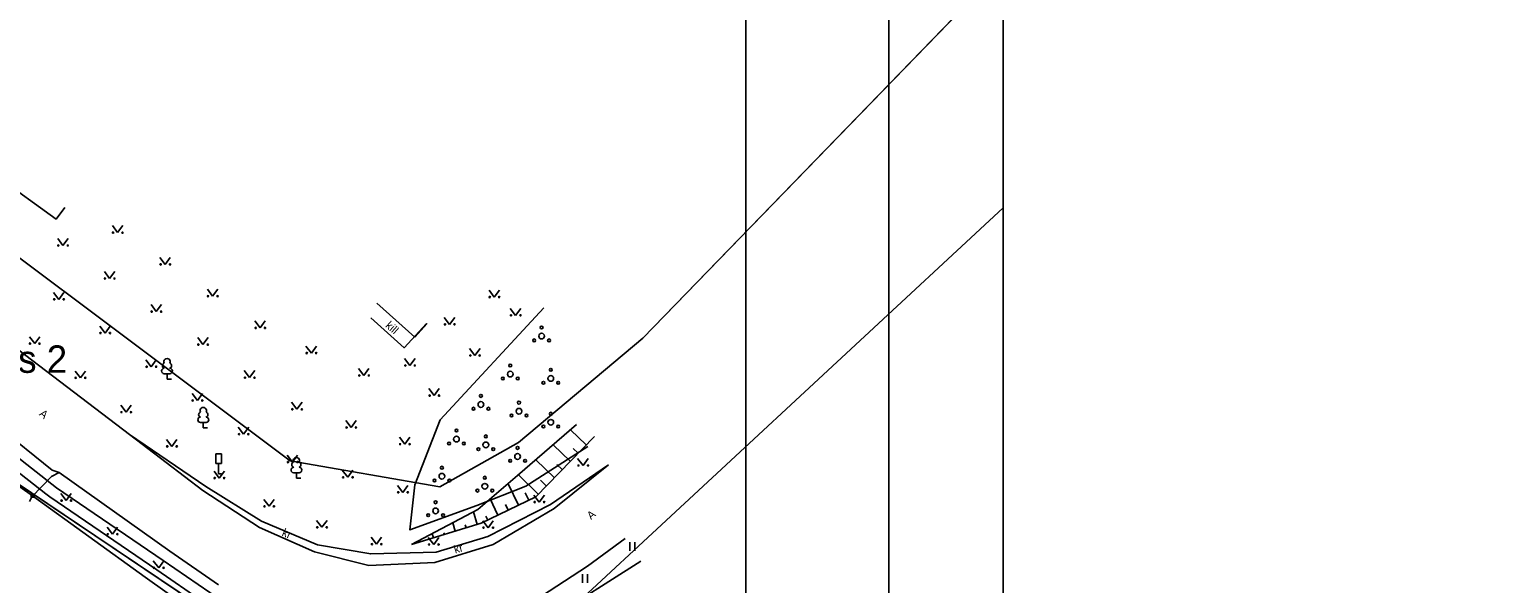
# Model space of a CAD drawing. Extents: x 554947 to 555436, y 6564938 to 6565792.
# Drawn here: x 555307.9 to 555435.7, y 6565528.1 to 6565576.6 of the extents above; entities that cross this region are included whole.
import ezdxf

# ---------------------------------------------------------------- set-up
doc = ezdxf.new("R2010")
doc.units = 0
for name, color, linetype in [('AED', 7, 'Continuous'), ('HALJASTUS', 7, 'Continuous'), ('KASUTUSALA', 7, 'Continuous'), ('LIIKLUS', 7, 'Continuous'), ('PIIR', 7, 'Continuous'), ('PR_SIDE', 7, 'Continuous'), ('PUU', 7, 'Continuous'), ('RELJEEF', 7, 'Continuous'), ('TEE', 7, 'Continuous'), ('VORMISTUS_3', 7, 'Continuous')]:
    doc.layers.add(name, color=color, linetype=linetype)

msp = doc.modelspace()

# ---------------------------------------------------------------- linework, layer by layer
at = {"layer": 'AED'}
for p, q in [((555304.52, 6565538.35), (555308.2, 6565535.79)), ((555308.07, 6565535.91), (555308.07, 6565535.66)), ((555308.07, 6565535.91), (555308.32, 6565535.91)), ((555308.32, 6565535.91), (555308.32, 6565535.66)), ((555308.07, 6565535.66), (555308.32, 6565535.66))]:
    msp.add_line(p, q, dxfattribs=at)
for points in [[(555338.31, 6565552.64), (555341.62, 6565549.67), (555342.69, 6565550.85)], [(555324, 6565524.39), (555318.05, 6565528.67), (555308.2, 6565535.79)]]:
    msp.add_lwpolyline(points, dxfattribs=at)
at = {"layer": 'HALJASTUS'}
for p, q in [((555315.17, 6565559.42), (555315.63, 6565558.81)), ((555315.63, 6565558.81), (555316.08, 6565559.42)), ((555310.39, 6565558.29), (555310.85, 6565557.68)), ((555310.85, 6565557.68), (555311.3, 6565558.29)), ((555319.32, 6565556.64), (555319.79, 6565556.03)), ((555319.79, 6565556.03), (555320.23, 6565556.64)), ((555314.47, 6565555.4), (555314.93, 6565554.79)), ((555314.93, 6565554.79), (555315.38, 6565555.4)), ((555323.48, 6565553.86), (555323.94, 6565553.25)), ((555323.94, 6565553.25), (555324.39, 6565553.86)), ((555310.03, 6565553.58), (555310.49, 6565552.97)), ((555310.49, 6565552.97), (555310.94, 6565553.58)), ((555348.11, 6565553.78), (555348.57, 6565553.17)), ((555348.57, 6565553.17), (555349.02, 6565553.78)), ((555318.55, 6565552.51), (555319.01, 6565551.9)), ((555319.01, 6565551.9), (555319.46, 6565552.51)), ((555344.2, 6565551.39), (555344.66, 6565550.78)), ((555344.66, 6565550.78), (555345.11, 6565551.39)), ((555349.97, 6565552.18), (555350.43, 6565551.57)), ((555350.43, 6565551.57), (555350.88, 6565552.18)), ((555314.07, 6565550.63), (555314.53, 6565550.02)), ((555314.53, 6565550.02), (555314.98, 6565550.63)), ((555327.63, 6565551.08), (555328.1, 6565550.47)), ((555328.1, 6565550.47), (555328.54, 6565551.08)), ((555307.91, 6565549.7), (555308.38, 6565549.1)), ((555308.38, 6565549.1), (555308.82, 6565549.7)), ((555322.63, 6565549.62), (555323.09, 6565549.01)), ((555323.09, 6565549.01), (555323.54, 6565549.62)), ((555332.1, 6565548.88), (555332.57, 6565548.27)), ((555332.57, 6565548.27), (555333.01, 6565548.88)), ((555318.11, 6565547.68), (555318.57, 6565547.07)), ((555318.57, 6565547.07), (555319.01, 6565547.68)), ((555340.73, 6565547.79), (555341.19, 6565547.18)), ((555341.19, 6565547.18), (555341.64, 6565547.79)), ((555346.41, 6565548.67), (555346.88, 6565548.06)), ((555346.88, 6565548.06), (555347.32, 6565548.67)), ((555311.91, 6565546.7), (555312.38, 6565546.1)), ((555312.38, 6565546.1), (555312.82, 6565546.7)), ((555326.71, 6565546.73), (555327.17, 6565546.12)), ((555327.17, 6565546.12), (555327.62, 6565546.73)), ((555336.7, 6565546.92), (555337.17, 6565546.31)), ((555337.17, 6565546.31), (555337.61, 6565546.92)), ((555342.85, 6565545.16), (555343.32, 6565544.55)), ((555343.32, 6565544.55), (555343.76, 6565545.16)), ((555315.91, 6565543.7), (555316.37, 6565543.1)), ((555316.37, 6565543.1), (555316.82, 6565543.7)), ((555322.14, 6565544.73), (555322.61, 6565544.12)), ((555322.61, 6565544.12), (555323.05, 6565544.73)), ((555330.85, 6565543.96), (555331.31, 6565543.35)), ((555331.31, 6565543.35), (555331.76, 6565543.96)), ((555335.59, 6565542.37), (555336.05, 6565541.76)), ((555336.05, 6565541.76), (555336.5, 6565542.37)), ((555326.18, 6565541.78), (555326.64, 6565541.17)), ((555326.64, 6565541.17), (555327.09, 6565541.78)), ((555319.91, 6565540.7), (555320.37, 6565540.1)), ((555320.37, 6565540.1), (555320.82, 6565540.7)), ((555340.28, 6565540.91), (555340.74, 6565540.3)), ((555340.74, 6565540.3), (555341.19, 6565540.91)), ((555330.46, 6565539.34), (555330.93, 6565538.73)), ((555330.93, 6565538.73), (555331.37, 6565539.34)), ((555355.86, 6565539.03), (555356.33, 6565538.43)), ((555356.33, 6565538.43), (555356.77, 6565539.03)), ((555324.06, 6565537.93), (555324.52, 6565537.33)), ((555324.52, 6565537.33), (555324.97, 6565537.93)), ((555335.28, 6565538.01), (555335.75, 6565537.4)), ((555335.75, 6565537.4), (555336.19, 6565538.01)), ((555310.67, 6565535.97), (555311.13, 6565535.36)), ((555311.13, 6565535.36), (555311.58, 6565535.97)), ((555340.1, 6565536.68), (555340.57, 6565536.08)), ((555340.57, 6565536.08), (555341.01, 6565536.68)), ((555328.41, 6565535.46), (555328.87, 6565534.86)), ((555328.87, 6565534.86), (555329.32, 6565535.46)), ((555352.04, 6565535.83), (555352.5, 6565535.23)), ((555352.5, 6565535.23), (555352.95, 6565535.83)), ((555333.03, 6565533.63), (555333.49, 6565533.02)), ((555333.49, 6565533.02), (555333.94, 6565533.63)), ((555347.57, 6565533.59), (555348.03, 6565532.99)), ((555348.03, 6565532.99), (555348.48, 6565533.59)), ((555314.71, 6565533.03), (555315.17, 6565532.42)), ((555315.17, 6565532.42), (555315.62, 6565533.03)), ((555337.81, 6565532.15), (555338.27, 6565531.55)), ((555338.27, 6565531.55), (555338.72, 6565532.15)), ((555342.8, 6565532.13), (555343.27, 6565531.52)), ((555343.27, 6565531.52), (555343.71, 6565532.13)), ((555360.41, 6565531.73), (555360.41, 6565530.97)), ((555360.86, 6565531.73), (555360.86, 6565530.97)), ((555318.75, 6565530.09), (555319.22, 6565529.48)), ((555319.22, 6565529.48), (555319.66, 6565530.09)), ((555356.27, 6565528.92), (555356.27, 6565528.16)), ((555356.72, 6565528.92), (555356.72, 6565528.16))]:
    msp.add_line(p, q, dxfattribs=at)
for points in [[(555352.89, 6565552.22), (555343.84, 6565542.42), (555341.63, 6565536.75), (555341.19, 6565532.8), (555347.05, 6565534.92), (555351.32, 6565536.63), (555356.76, 6565540.09)], [(555361.38, 6565530.07), (555353.3, 6565524.93), (555351.72, 6565521.85), (555350.97, 6565518.73), (555353.48, 6565515.91)]]:
    msp.add_lwpolyline(points, dxfattribs=at)
for centre in [(555310.45, 6565557.68), (555311.28, 6565557.68), (555315.23, 6565558.81), (555316.06, 6565558.81), (555319.39, 6565556.03), (555320.21, 6565556.03), (555314.53, 6565554.79), (555315.36, 6565554.79), (555310.09, 6565552.97), (555310.92, 6565552.97), (555323.54, 6565553.25), (555324.37, 6565553.25), (555348.17, 6565553.17), (555349, 6565553.17), (555318.61, 6565551.9), (555319.44, 6565551.9), (555350.03, 6565551.57), (555350.86, 6565551.57), (555314.13, 6565550.02), (555314.96, 6565550.02), (555327.7, 6565550.47), (555328.52, 6565550.47), (555344.26, 6565550.78), (555345.09, 6565550.78), (555307.97, 6565549.1), (555308.8, 6565549.1), (555322.69, 6565549.01), (555323.52, 6565549.01), (555332.17, 6565548.27), (555332.99, 6565548.27), (555346.47, 6565548.06), (555347.3, 6565548.06), (555311.97, 6565546.1), (555312.8, 6565546.1), (555318.17, 6565547.07), (555319, 6565547.07), (555326.77, 6565546.12), (555327.6, 6565546.12), (555336.77, 6565546.31), (555337.6, 6565546.31), (555340.79, 6565547.18), (555341.62, 6565547.18), (555322.2, 6565544.12), (555323.03, 6565544.12), (555342.92, 6565544.55), (555343.74, 6565544.55), (555315.97, 6565543.1), (555316.8, 6565543.1), (555330.91, 6565543.35), (555331.74, 6565543.35), (555326.24, 6565541.17), (555327.07, 6565541.17), (555335.65, 6565541.76), (555336.48, 6565541.76), (555319.97, 6565540.1), (555320.8, 6565540.1), (555340.34, 6565540.3), (555341.17, 6565540.3), (555330.53, 6565538.73), (555331.36, 6565538.73), (555355.93, 6565538.43), (555356.76, 6565538.43), (555324.12, 6565537.33), (555324.95, 6565537.33), (555335.35, 6565537.4), (555336.18, 6565537.4), (555340.17, 6565536.08), (555341, 6565536.08), (555310.73, 6565535.36), (555311.56, 6565535.36), (555328.47, 6565534.86), (555329.3, 6565534.86), (555352.1, 6565535.23), (555352.93, 6565535.23), (555314.77, 6565532.42), (555315.6, 6565532.42), (555333.09, 6565533.02), (555333.92, 6565533.02), (555347.63, 6565532.99), (555348.46, 6565532.99), (555337.87, 6565531.55), (555338.7, 6565531.55), (555342.87, 6565531.52), (555343.7, 6565531.52), (555318.82, 6565529.48), (555319.65, 6565529.48)]:
    msp.add_circle(centre, 0.055, dxfattribs=at)
at = {"layer": 'KASUTUSALA'}
msp.add_lwpolyline([(555304.52, 6565541), (555310.28, 6565536.49), (555319.62, 6565530.13), (555323.68, 6565527.32), (555324.11, 6565527.04), (555330.04, 6565523.57), (555332.04, 6565522.33), (555334.88, 6565520.64), (555337.95, 6565518.8), (555340.91, 6565516.06), (555343.38, 6565512.73), (555343.14, 6565512.46), (555338.79, 6565515.38), (555330.79, 6565520.76), (555305.2, 6565537.96)], dxfattribs=at)
at = {"layer": 'LIIKLUS'}
for p, q in [((555324.21, 6565539.45), (555324.21, 6565538.6)), ((555324.71, 6565539.45), (555324.21, 6565539.45)), ((555324.71, 6565538.6), (555324.21, 6565538.6)), ((555324.46, 6565538.6), (555324.46, 6565537.7)), ((555324.71, 6565539.45), (555324.71, 6565538.6)), ((555324.71, 6565537.7), (555324.46, 6565537.7))]:
    msp.add_line(p, q, dxfattribs=at)
at = {"layer": 'PIIR'}
for points in [[(555374.15, 6565660.24), (555410.9, 6565638.65), (555418.94, 6565635.85), (555435.71, 6565632.72), (555428.83, 6565620.98), (555419.65, 6565609.54), (555361.56, 6565549.57), (555350.68, 6565540.44), (555343.81, 6565536.56), (555330.71, 6565538.85), (555251.24, 6565598.48), (555234.35, 6565605.6), (555223.17, 6565668.21)], [(555144.16, 6565410.6), (555124.27, 6565454.45), (555113.82, 6565475.68), (555076.76, 6565542.38), (555065.78, 6565566.7), (555060.42, 6565583.26), (555057.22, 6565600.73), (555056.61, 6565622.91), (555063.43, 6565647.29), (555114.24, 6565634), (555129.77, 6565611.2), (555130.73, 6565621.32), (555138.66, 6565615.26), (555160.12, 6565598.86), (555193.24, 6565604.68), (555193.7, 6565602.7), (555225.47, 6565605.89), (555234.35, 6565605.6), (555251.24, 6565598.48), (555330.71, 6565538.85), (555343.81, 6565536.56), (555350.68, 6565540.44), (555361.56, 6565549.57), (555393.07, 6565582.1)], [(555393.07, 6565560.97), (555353.12, 6565523.87), (555343.14, 6565512.46), (555302.6, 6565539.71), (555242.37, 6565583.94), (555179.42, 6565586.32), (555138.98, 6565580.6), (555121.18, 6565602.26), (555116.17, 6565610.5), (555109.96, 6565624.83), (555093.56, 6565628.47), (555079.04, 6565618.4), (555074.13, 6565607.82), (555075.34, 6565593.24), (555091.74, 6565551.94), (555171.91, 6565394.64), (555191.35, 6565341.19), (555195.08, 6565294.61), (555195.28, 6565271.63), (555191.64, 6565237.48)], [(555393.07, 6565456.05), (555368.05, 6565461.11), (555358.8, 6565482.45), (555353.12, 6565523.87), (555393.07, 6565560.97)]]:
    msp.add_lwpolyline(points, dxfattribs=at)
msp.add_lwpolyline([(555153.01, 6565448.47), (555161.15, 6565451.45), (555173.66, 6565456.03), (555207.29, 6565506.14), (555287.77, 6565518.56), (555302.6, 6565539.71), (555343.14, 6565512.46), (555319.44, 6565481.04), (555323.07, 6565461.26), (555312.9, 6565433.84), (555316.84, 6565372.52), (555318.72, 6565342.57), (555320.51, 6565314.61), (555303.13, 6565302.54), (555208.78, 6565303.3), (555205.15, 6565297.11), (555200.72, 6565310.3), (555206.9, 6565339.44), (555221.23, 6565376.06), (555216.83, 6565392.35), (555207.22, 6565406.57)], close=True, dxfattribs=at)
at = {"layer": 'PR_SIDE'}
msp.add_lwpolyline([(555383.07, 6565448.91), (555372.33, 6565450.45), (555366.01, 6565452.34), (555363.26, 6565453.63), (555360.29, 6565456.79), (555356.82, 6565461.86), (555354.2, 6565468.75), (555353.75, 6565469.93), (555350.28, 6565487.81), (555348.6, 6565498.75), (555346.2, 6565508), (555346.03, 6565508.33), (555343.44, 6565510.97), (555340.16, 6565515.39), (555337.34, 6565518), (555334.37, 6565519.78), (555331.52, 6565521.47), (555329.52, 6565522.71), (555323.59, 6565526.19), (555323.12, 6565526.49), (555319.05, 6565529.3), (555309.69, 6565535.68), (555309.35, 6565535.94), (555304.35, 6565539.86)], dxfattribs=at)
at = {"layer": 'PUU'}
for p, q in [((555320.19, 6565546.46), (555319.71, 6565546.46)), ((555319.95, 6565545.99), (555319.95, 6565546.46)), ((555320.33, 6565545.99), (555319.95, 6565545.99)), ((555323.36, 6565542.2), (555322.88, 6565542.2)), ((555323.12, 6565541.72), (555323.12, 6565542.2)), ((555323.5, 6565541.72), (555323.12, 6565541.72)), ((555331.5, 6565537.8), (555331.02, 6565537.8)), ((555331.26, 6565537.33), (555331.26, 6565537.8)), ((555331.64, 6565537.33), (555331.26, 6565537.33))]:
    msp.add_line(p, q, dxfattribs=at)
for centre, radius in [((555352.71, 6565549.76), 0.25), ((555352.71, 6565550.51), 0.125), ((555352.06, 6565549.38), 0.125), ((555353.36, 6565549.38), 0.125), ((555349.32, 6565546.05), 0.125), ((555349.97, 6565546.43), 0.25), ((555349.97, 6565547.18), 0.125), ((555350.62, 6565546.05), 0.125), ((555353.51, 6565546.05), 0.25), ((555353.51, 6565546.8), 0.125), ((555352.86, 6565545.67), 0.125), ((555354.16, 6565545.67), 0.125), ((555347.4, 6565543.77), 0.25), ((555347.4, 6565544.52), 0.125), ((555350.73, 6565543.93), 0.125), ((555346.75, 6565543.4), 0.125), ((555348.05, 6565543.4), 0.125), ((555350.08, 6565542.81), 0.125), ((555350.73, 6565543.18), 0.25), ((555351.38, 6565542.81), 0.125), ((555353.51, 6565542.21), 0.25), ((555353.51, 6565542.96), 0.125), ((555345.26, 6565541.49), 0.125), ((555347.83, 6565540.98), 0.125), ((555352.86, 6565541.84), 0.125), ((555354.16, 6565541.84), 0.125), ((555344.61, 6565540.36), 0.125), ((555345.26, 6565540.74), 0.25), ((555345.91, 6565540.36), 0.125), ((555347.18, 6565539.86), 0.125), ((555347.83, 6565540.23), 0.25), ((555348.48, 6565539.86), 0.125), ((555350.61, 6565539.97), 0.125), ((555349.96, 6565538.84), 0.125), ((555350.61, 6565539.22), 0.25), ((555351.26, 6565538.84), 0.125), ((555343.34, 6565537.12), 0.125), ((555343.99, 6565537.49), 0.25), ((555343.99, 6565538.24), 0.125), ((555344.64, 6565537.12), 0.125), ((555347.74, 6565537.36), 0.125), ((555347.09, 6565536.23), 0.125), ((555347.74, 6565536.61), 0.25), ((555348.39, 6565536.23), 0.125), ((555343.44, 6565534.46), 0.25), ((555343.44, 6565535.21), 0.125), ((555342.79, 6565534.08), 0.125), ((555344.09, 6565534.08), 0.125)]:
    msp.add_circle(centre, radius, dxfattribs=at)
for centre, radius, start, end in [((555319.95, 6565547.51), 0.277, 332.5799, 207.4201), ((555319.71, 6565546.7), 0.238, 90.0016, 269.3953), ((555319.78, 6565547.16), 0.233, 109.0217, 253.1415), ((555320.12, 6565547.16), 0.233, 286.8508, 70.9859), ((555320.18, 6565546.7), 0.238, 270.6047, 89.9984), ((555322.88, 6565542.43), 0.238, 90.0016, 269.3953), ((555322.95, 6565542.89), 0.233, 109.0217, 253.1415), ((555323.12, 6565543.24), 0.277, 332.5799, 207.4201), ((555323.29, 6565542.89), 0.233, 286.8508, 70.9859), ((555323.36, 6565542.43), 0.238, 270.6047, 89.9984), ((555331.09, 6565538.5), 0.233, 109.0217, 253.1415), ((555331.26, 6565538.85), 0.277, 332.5799, 207.4201), ((555331.43, 6565538.5), 0.233, 286.8508, 70.9859), ((555331.03, 6565538.04), 0.238, 90.0016, 269.3953), ((555331.5, 6565538.04), 0.238, 270.6047, 89.9984)]:
    msp.add_arc(centre, radius, start, end, dxfattribs=at)
at = {"layer": 'RELJEEF'}
for p, q in [((555356.6, 6565540.23), (555355.24, 6565541.56)), ((555355.21, 6565538.8), (555353.72, 6565540.25)), ((555355.91, 6565539.52), (555355.48, 6565539.93)), ((555353.82, 6565537.36), (555352.2, 6565538.93)), ((555354.51, 6565538.08), (555354.05, 6565538.53)), ((555352.42, 6565535.93), (555350.68, 6565537.62)), ((555350.69, 6565534.96), (555349.78, 6565536.84)), ((555351.59, 6565535.4), (555351.28, 6565536.03)), ((555353.12, 6565536.65), (555352.62, 6565537.14)), ((555348.89, 6565534.09), (555348.21, 6565535.5)), ((555349.79, 6565534.52), (555349.55, 6565535.02)), ((555345.16, 6565532.68), (555344.94, 6565533.42)), ((555347.07, 6565533.26), (555346.74, 6565534.37)), ((555347.99, 6565533.65), (555347.82, 6565534)), ((555343.25, 6565532.1), (555343.14, 6565532.46)), ((555344.21, 6565532.39), (555344.16, 6565532.55)), ((555346.12, 6565532.97), (555346.03, 6565533.25)), ((555342.29, 6565531.8), (555342.28, 6565531.86))]:
    msp.add_line(p, q, dxfattribs=at)
for points in [[(555341.34, 6565531.51), (555347.14, 6565534.58), (555350.61, 6565537.56), (555355.77, 6565542.02)], [(555341.34, 6565531.51), (555347.42, 6565533.37), (555352.19, 6565535.69), (555357.33, 6565540.98)]]:
    msp.add_lwpolyline(points, dxfattribs=at)
at = {"layer": 'TEE'}
for points in [[(555272.68, 6565590.13), (555271.48, 6565588.08), (555270.52, 6565586.42), (555269.72, 6565584.61), (555268.98, 6565582.24), (555268.55, 6565578.95), (555269.5, 6565576.95), (555281.04, 6565568.1), (555297.77, 6565555.51), (555316.66, 6565541.13), (555323.07, 6565536.25), (555328.04, 6565533.01), (555332.84, 6565530.88), (555337.61, 6565529.69), (555343.36, 6565529.95), (555348.46, 6565531.53), (555353.8, 6565534.68), (555358.56, 6565538.5)], [(555293.36, 6565574.44), (555292.54, 6565573.05), (555305.07, 6565563.71), (555310.25, 6565559.99), (555311.01, 6565561)], [(555337.76, 6565551.34), (555340.69, 6565548.73), (555342.63, 6565550.87)], [(555324.45, 6565528), (555320.2, 6565530.94), (555310.53, 6565537.81), (555309.91, 6565538.03), (555305.17, 6565541.81)], [(555316.66, 6565541.13), (555323.34, 6565536.58), (555328.21, 6565533.55), (555333.12, 6565531.48), (555337.76, 6565530.7), (555343.48, 6565530.86), (555348.01, 6565532.22), (555353.48, 6565535.01), (555358.56, 6565538.5)], [(555310.53, 6565537.81), (555309.86, 6565537.47), (555308.14, 6565535.69), (555307.92, 6565535.29)], [(555360.02, 6565532.03), (555356.72, 6565529.61), (555352.04, 6565526.57), (555350.84, 6565524.29), (555349.9, 6565522.25), (555349.37, 6565518.74), (555349.97, 6565514.97), (555351.5, 6565509.51), (555352.4, 6565505.44), (555355.18, 6565489.69), (555356.36, 6565481.87), (555358.54, 6565472.03), (555360.2, 6565467.29), (555362.13, 6565463.39), (555365, 6565459.53), (555367.92, 6565457.75), (555371.76, 6565456.51), (555378.11, 6565454.85), (555393.07, 6565452.68)]]:
    msp.add_lwpolyline(points, dxfattribs=at)
at = {"layer": 'VORMISTUS_3'}
for points in [[(555183.07, 6565701.75), (555393.07, 6565701.75), (555393.07, 6565404.75), (555183.07, 6565404.75)], [(555193.07, 6565415.75), (555383.07, 6565415.75), (555383.07, 6565690.75), (555193.07, 6565690.75)], [(555193.07, 6565690.75), (555383.07, 6565690.75), (555383.07, 6565415.75), (555193.07, 6565415.75)], [(555370.57, 6565441.75), (555205.57, 6565441.75), (555205.57, 6565651.75), (555370.57, 6565651.75)]]:
    msp.add_lwpolyline(points, close=True, dxfattribs=at)

# ---------------------------------------------------------------- texts
at = {"layer": 'TEE'}
for s, rotation, p in [('kill', 318.3864, (555339, 6565550.6)), ('A', 320.7112, (555308.71, 6565542.86)), ('A', 40.0399, (555357.03, 6565533.65)), ('kr', 336.0366, (555329.94, 6565532.31)), ('kr', 17.2462, (555345.16, 6565530.72))]:
    msp.add_text(s, height=0.7, rotation=rotation, dxfattribs=at).set_placement(p)
at = {"layer": 'VORMISTUS_3'}
msp.add_text('Pos 2', height=2.4, dxfattribs=at).set_placement((555303.01, 6565546.54))

doc.saveas('drawing.dxf')
